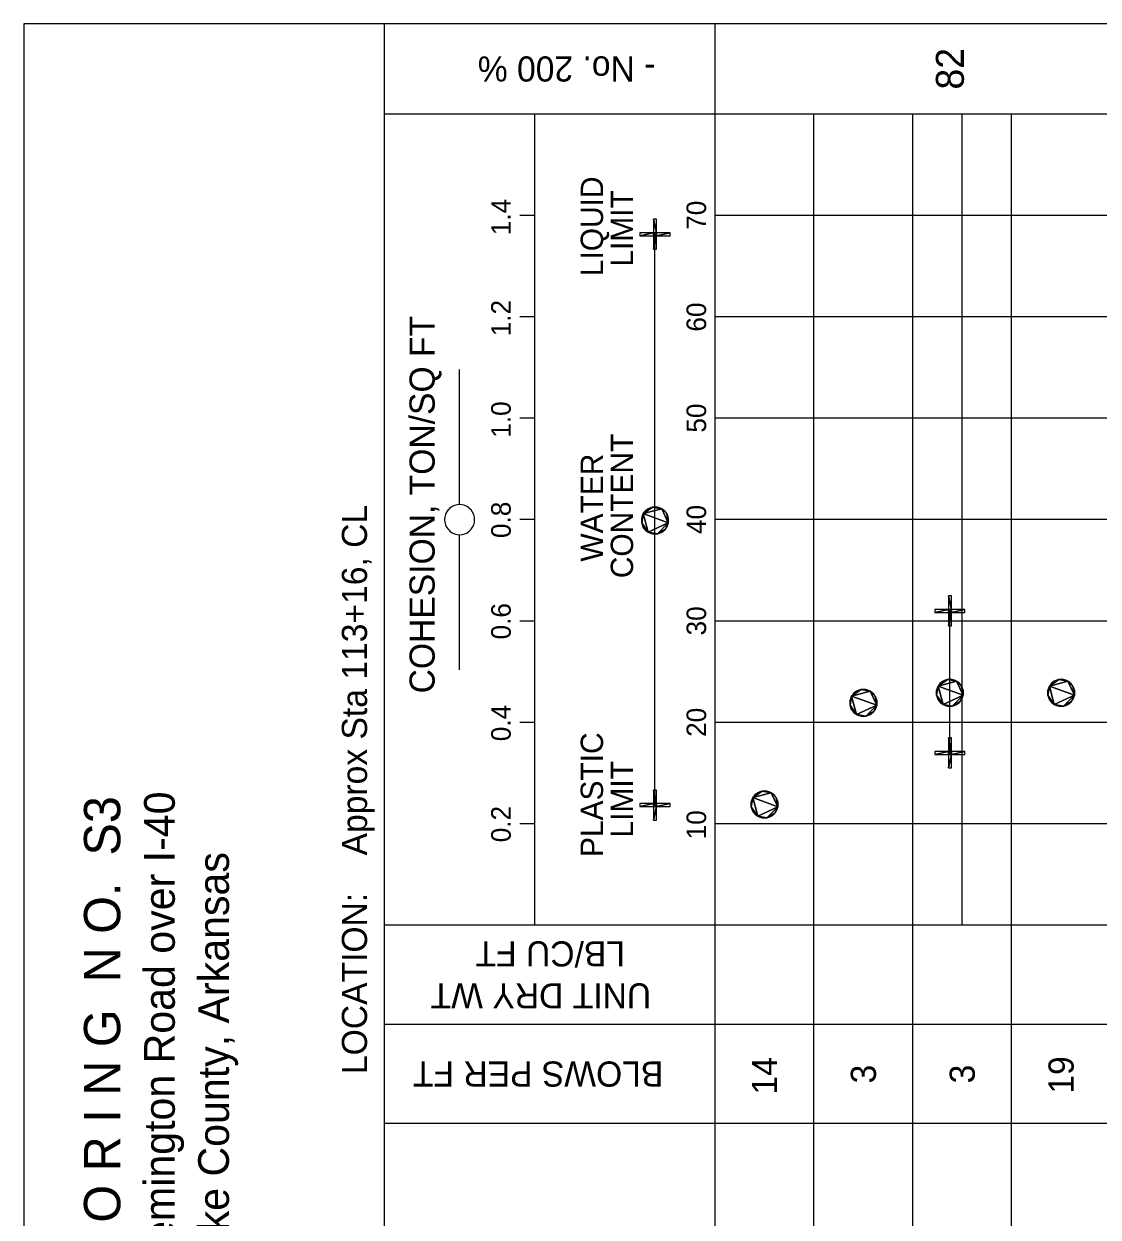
# Model space of a CAD drawing. Extents: x 1313964 to 1316843, y 2087046 to 2096619.
# Drawn here: x 1314173.48 to 1314195.22, y 2089892.16 to 2089916.31 of the extents above; entities that cross this region are included whole.
import ezdxf

# ---------------------------------------------------------------- set-up
doc = ezdxf.new("R2010")
doc.units = 0
doc.layers.add('B-Sub-Contour', color=7, linetype='Continuous')
doc.layers.add('Default', color=7, linetype='Continuous')

# ---------------------------------------------------------------- blocks, each defined once
blk = doc.blocks.new('POINT_DISPLAY')
at = {"layer": 'Default'}
blk.add_line((0, 0), (0, 0), dxfattribs=at)
blk = doc.blocks.new('DMK_101')
at = {"layer": 'Default'}
for points in [[(-3147.06, 13511.784), (-7618.476, 11878.056), (-12638.532, 6858), (-3147.06, 13511.784)], [(6097.524, 11878.056), (-3147.06, 13511.784), (-12638.532, 6858), (6097.524, 11878.056)], [(-3147.06, 13511.784), (-5451.348, 12893.04), (-7618.476, 11878.056), (-3147.06, 13511.784)], [(1626.108, 13511.784), (-760.476, 13712.952), (-3147.06, 13511.784), (1626.108, 13511.784)], [(6097.524, 11878.056), (1626.108, 13511.784), (-3147.06, 13511.784), (6097.524, 11878.056)], [(6097.524, 11878.056), (3930.396, 12893.04), (1626.108, 13511.784), (6097.524, 11878.056)], [(-14269.212, 2386.584), (-14476.476, 0), (-14269.212, -2386.584), (-14269.212, 2386.584)], [(-12638.532, 6858), (-13653.516, 4690.872), (-14269.212, 2386.584), (-12638.532, 6858)], [(-12638.532, 6858), (-14269.212, 2386.584), (-14269.212, -2386.584), (-12638.532, 6858)], [(-12638.532, 6858), (-14269.212, -2386.584), (-3147.06, -13508.736), (-12638.532, 6858)], [(-7618.476, 11878.056), (-11266.932, 8820.912), (-12638.532, 6858), (-7618.476, 11878.056)], [(-3147.06, -13508.736), (6097.524, 11878.056), (-12638.532, 6858), (-3147.06, -13508.736)], [(-7618.476, 11878.056), (-9578.34, 10506.456), (-11266.932, 8820.912), (-7618.476, 11878.056)], [(-9578.34, 10506.456), (-10456.164, 9698.736), (-11266.932, 8820.912), (-9578.34, 10506.456)], [(-3147.06, -13508.736), (11117.58, -6858), (6097.524, 11878.056), (-3147.06, -13508.736)], [(11117.58, 6858), (8060.436, 10506.456), (6097.524, 11878.056), (11117.58, 6858)], [(12751.308, 2386.584), (11117.58, 6858), (6097.524, 11878.056), (12751.308, 2386.584)], [(11117.58, -6858), (12751.308, 2386.584), (6097.524, 11878.056), (11117.58, -6858)], [(9745.98, 8820.912), (8938.26, 9698.736), (8060.436, 10506.456), (9745.98, 8820.912)], [(11117.58, 6858), (9745.98, 8820.912), (8060.436, 10506.456), (11117.58, 6858)], [(12751.308, 2386.584), (12132.564, 4690.872), (11117.58, 6858), (12751.308, 2386.584)], [(11117.58, -6858), (12751.308, -2386.584), (12751.308, 2386.584), (11117.58, -6858)], [(12751.308, -2386.584), (12952.476, 0), (12751.308, 2386.584), (12751.308, -2386.584)], [(-14269.212, -2386.584), (-13653.516, -4690.872), (-12638.532, -6858), (-14269.212, -2386.584)], [(-14269.212, -2386.584), (-12638.532, -6858), (-9578.34, -10506.456), (-14269.212, -2386.584)], [(-14269.212, -2386.584), (-9578.34, -10506.456), (-3147.06, -13508.736), (-14269.212, -2386.584)], [(-12638.532, -6858), (-11266.932, -8817.864), (-9578.34, -10506.456), (-12638.532, -6858)], [(-11266.932, -8817.864), (-10456.164, -9695.688), (-9578.34, -10506.456), (-11266.932, -8817.864)], [(-9578.34, -10506.456), (-7618.476, -11878.056), (-3147.06, -13508.736), (-9578.34, -10506.456)], [(-7618.476, -11878.056), (-5451.348, -12893.04), (-3147.06, -13508.736), (-7618.476, -11878.056)], [(-3147.06, -13508.736), (6097.524, -11878.056), (11117.58, -6858), (-3147.06, -13508.736)], [(-3147.06, -13508.736), (1626.108, -13508.736), (6097.524, -11878.056), (-3147.06, -13508.736)], [(1626.108, -13508.736), (3930.396, -12893.04), (6097.524, -11878.056), (1626.108, -13508.736)], [(6097.524, -11878.056), (8060.436, -10506.456), (11117.58, -6858), (6097.524, -11878.056)], [(8060.436, -10506.456), (9745.98, -8817.864), (11117.58, -6858), (8060.436, -10506.456)], [(8060.436, -10506.456), (8938.26, -9695.688), (9745.98, -8817.864), (8060.436, -10506.456)], [(11117.58, -6858), (12132.564, -4690.872), (12751.308, -2386.584), (11117.58, -6858)], [(-3147.06, -13508.736), (-760.476, -13716), (1626.108, -13508.736), (-3147.06, -13508.736)]]:
    blk.add_lwpolyline(points, close=True, dxfattribs=at)
blk.add_blockref('POINT_DISPLAY', (14479.524, 0), dxfattribs=at)
blk = doc.blocks.new('DMK_99')
at = {"layer": 'Default'}
for points in [[(1524, 1524), (1524, 15240), (-1524, 15240), (1524, 1524)], [(1524, 1524), (-1524, 15240), (-1524, 1524), (1524, 1524)], [(-1524, -1524), (-1524, 1524), (-15240, 1524), (-1524, -1524)], [(-1524, -1524), (-15240, 1524), (-15240, -1524), (-1524, -1524)], [(-1524, -1524), (1524, -1524), (1524, 1524), (-1524, -1524)], [(-1524, -1524), (1524, 1524), (-1524, 1524), (-1524, -1524)], [(1524, -1524), (15240, -1524), (15240, 1524), (1524, -1524)], [(1524, -1524), (15240, 1524), (1524, 1524), (1524, -1524)], [(-1524, -1524), (-1524, -15240), (1524, -15240), (-1524, -1524)], [(-1524, -1524), (1524, -15240), (1524, -1524), (-1524, -1524)]]:
    blk.add_lwpolyline(points, close=True, dxfattribs=at)
blk = doc.blocks.new('DMK_7')
at = {"layer": 'Default'}
blk.add_lwpolyline([(0, -15240), (2651.76, -15011.4), (5212.08, -14325.6), (7620, -13197.84), (9799.32, -11673.84), (10774.68, -10774.68), (11673.84, -9799.32), (13197.84, -7620), (14325.6, -5212.08), (15011.4, -2651.76), (15240, 0), (15011.4, 2651.76), (14325.6, 5212.08), (13197.84, 7620), (11673.84, 9799.32), (10774.68, 10774.68), (9799.32, 11673.84), (7620, 13197.84), (5212.08, 14325.6), (2651.76, 15011.4), (0, 15240), (-2651.76, 15011.4), (-5212.08, 14325.6), (-7620, 13197.84), (-9799.32, 11673.84), (-10774.68, 10774.68), (-11673.84, 9799.32), (-13197.84, 7620), (-14325.6, 5212.08), (-15011.4, 2651.76), (-15240, 0), (-15011.4, -2651.76), (-14325.6, -5212.08), (-13197.84, -7620), (-11673.84, -9799.32), (-10774.68, -10774.68), (-9799.32, -11673.84), (-7620, -13197.84), (-5212.08, -14325.6), (-2651.76, -15011.4), (0, -15240)], dxfattribs=at)

msp = doc.modelspace()

# ---------------------------------------------------------------- linework, layer by layer
at = {"layer": 'B-Sub-Contour'}
for points in [[(1314234.904, 2089873.434), (1314234.904, 2089916.306), (1314173.485, 2089916.306), (1314173.485, 2089873.434), (1314234.904, 2089873.434)], [(1314180.782, 2089873.434), (1314180.782, 2089916.306)], [(1314187.471, 2089873.434), (1314187.471, 2089916.306)], [(1314232.471, 2089914.481), (1314180.782, 2089914.481)], [(1314183.823, 2089914.481), (1314183.519, 2089914.481)], [(1314183.823, 2089898.063), (1314183.823, 2089914.481)], [(1314232.471, 2089914.481), (1314187.471, 2089914.481)], [(1314187.471, 2089898.063), (1314187.471, 2089914.481)], [(1314189.471, 2089894.049), (1314189.471, 2089914.481)], [(1314191.471, 2089894.049), (1314191.471, 2089914.481)], [(1314192.471, 2089898.063), (1314192.471, 2089914.481)], [(1314193.471, 2089894.049), (1314193.471, 2089914.481)], [(1314183.823, 2089912.429), (1314183.519, 2089912.429)], [(1314232.471, 2089912.429), (1314187.471, 2089912.429)], [(1314186.255, 2089900.495), (1314186.255, 2089912.049)], [(1314183.823, 2089910.377), (1314183.519, 2089910.377)], [(1314232.471, 2089910.377), (1314187.471, 2089910.377)], [(1314182.302, 2089906.576), (1314182.302, 2089909.313)], [(1314183.823, 2089908.324), (1314183.519, 2089908.324)], [(1314232.471, 2089908.324), (1314187.471, 2089908.324)], [(1314183.823, 2089906.272), (1314183.519, 2089906.272)], [(1314232.471, 2089906.272), (1314187.471, 2089906.272)], [(1314182.302, 2089903.232), (1314182.302, 2089905.968)], [(1314192.221, 2089901.552), (1314192.221, 2089904.425)], [(1314192.221, 2089901.552), (1314192.221, 2089904.425)], [(1314183.823, 2089904.22), (1314183.519, 2089904.22)], [(1314232.471, 2089904.22), (1314187.471, 2089904.22)], [(1314183.823, 2089902.167), (1314183.519, 2089902.167)], [(1314232.471, 2089902.167), (1314187.471, 2089902.167)], [(1314183.823, 2089900.115), (1314183.519, 2089900.115)], [(1314232.471, 2089900.115), (1314187.471, 2089900.115)], [(1314232.471, 2089898.063), (1314180.782, 2089898.063)], [(1314183.823, 2089898.063), (1314183.519, 2089898.063)], [(1314232.471, 2089898.063), (1314187.471, 2089898.063)], [(1314232.471, 2089896.056), (1314180.782, 2089896.056)], [(1314232.471, 2089894.049), (1314180.782, 2089894.049)], [(1314189.471, 2089878.178), (1314189.471, 2089894.049)], [(1314191.471, 2089878.178), (1314191.471, 2089894.049)], [(1314193.471, 2089878.178), (1314193.471, 2089894.049)]]:
    msp.add_lwpolyline(points, dxfattribs=at)

# ---------------------------------------------------------------- block references
at = {"layer": 'B-Sub-Contour', "xscale": 1.9951013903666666e-05, "yscale": 1.9951013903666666e-05, "rotation": 90}
for name, p in [('DMK_99', (1314186.255, 2089912.049)), ('DMK_7', (1314182.302, 2089906.272)), ('DMK_101', (1314186.255, 2089906.272)), ('DMK_99', (1314192.221, 2089904.425)), ('DMK_99', (1314192.221, 2089904.425)), ('DMK_101', (1314190.471, 2089902.578)), ('DMK_101', (1314190.471, 2089902.578)), ('DMK_101', (1314192.221, 2089902.783)), ('DMK_101', (1314192.221, 2089902.783)), ('DMK_101', (1314194.471, 2089902.783)), ('DMK_101', (1314194.471, 2089902.783)), ('DMK_99', (1314192.221, 2089901.552)), ('DMK_99', (1314192.221, 2089901.552)), ('DMK_99', (1314186.255, 2089900.495)), ('DMK_101', (1314188.471, 2089900.525)), ('DMK_101', (1314188.471, 2089900.525))]:
    msp.add_blockref(name, p, dxfattribs=at)

# ---------------------------------------------------------------- texts
at = {"layer": 'B-Sub-Contour'}
for s, height, rotation, p in [('82', 0.5655, 90, (1314192.504, 2089914.977)), ('- No. 200 %', 0.50899, 180, (1314186.263, 2089915.648)), ('LIQUID', 0.4524, 90, (1314185.204, 2089911.2)), ('LIMIT', 0.4524, 90, (1314185.812, 2089911.394)), ('1.4', 0.3959, 90, (1314183.336, 2089912.028)), ('70', 0.3959, 90, (1314187.289, 2089912.138)), ('1.2', 0.3959, 90, (1314183.336, 2089909.983)), ('60', 0.3959, 90, (1314187.289, 2089910.078)), ('COHESION, TON/SQ FT', 0.50899, 90, (1314181.797, 2089902.756)), ('1.0', 0.3959, 90, (1314183.336, 2089907.93)), ('50', 0.3959, 90, (1314187.289, 2089908.033)), ('CONTENT', 0.4524, 90, (1314185.812, 2089905.087)), ('WATER', 0.4524, 90, (1314185.204, 2089905.423)), ('LOCATION:    Approx Sta 113+16, CL', 0.50899, 90, (1314180.428, 2089895.052)), ('0.8', 0.3959, 90, (1314183.336, 2089905.9)), ('40', 0.3959, 90, (1314187.289, 2089905.981)), ('0.6', 0.3959, 90, (1314183.336, 2089903.848)), ('30', 0.3959, 90, (1314187.289, 2089903.929)), ('0.4', 0.3959, 90, (1314183.336, 2089901.788)), ('20', 0.3959, 90, (1314187.289, 2089901.876)), ('PLASTIC', 0.4524, 90, (1314185.204, 2089899.445)), ('LIMIT', 0.4524, 90, (1314185.812, 2089899.84)), ('061610 - Remington Road over I-40', 0.62209, 90, (1314176.539, 2089887.499)), ('L O G  O F  B O R I N G  N O.  S3', 0.7352, 90, (1314175.436, 2089885.763)), ('0.2', 0.3959, 90, (1314183.336, 2089899.743)), ('10', 0.3959, 90, (1314187.289, 2089899.802)), ('Lonoke County, Arkansas', 0.62209, 90, (1314177.634, 2089890.018)), ('LB/CU FT', 0.509, 180, (1314185.649, 2089897.739)), ('UNIT DRY WT', 0.50899, 180, (1314186.178, 2089896.888)), ('19', 0.509, 90, (1314194.726, 2089894.655)), ('BLOWS PER FT', 0.50899, 180, (1314186.424, 2089895.307)), ('14', 0.509, 90, (1314188.726, 2089894.637)), ('3', 0.509, 90, (1314190.726, 2089894.863)), ('3', 0.509, 90, (1314192.726, 2089894.863))]:
    msp.add_text(s, height=height, rotation=rotation, dxfattribs=at).set_placement(p)

doc.saveas('drawing.dxf')
